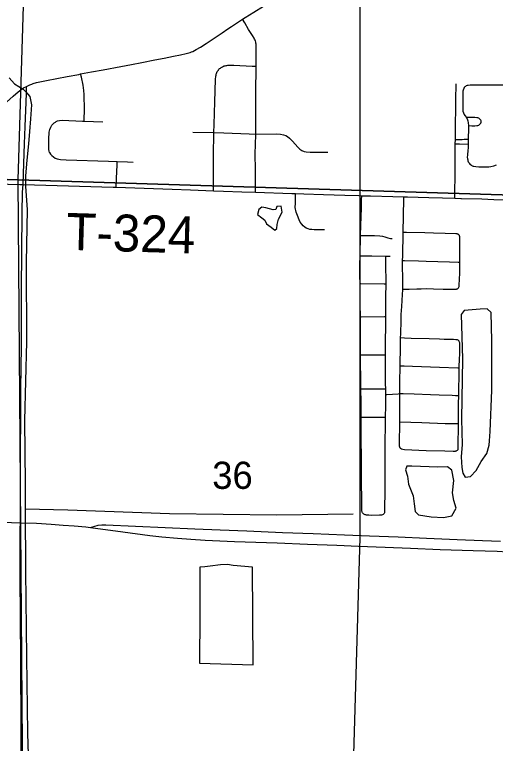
# Model space of a CAD drawing. Extents: x -59 to 43, y 0 to 22.
# Drawn here: x 24.142 to 24.882, y 15.472 to 16.594 of the extents above; entities that cross this region are included whole.
import ezdxf

# ---------------------------------------------------------------- set-up
doc = ezdxf.new("R2010")
doc.units = 0
for name, color, linetype in [('Default', 7, 'Continuous'), ('GM_X_City_Street', 7, 'Continuous'), ('GM_X_County_Road', 7, 'Continuous'), ('GM_X_Minor_Lake', 7, 'Continuous'), ('GM_X_Minor_River', 7, 'Continuous'), ('GM_X_Rail_Line', 7, 'Continuous'), ('GM_X_Section', 7, 'Continuous'), ('GM_X_Section_Text', 7, 'Continuous'), ('GM_X_Township_Road', 7, 'Continuous'), ('GM_X_Township_Road_Text', 7, 'Continuous'), ('GM_X_US_Route', 7, 'Continuous')]:
    doc.layers.add(name, color=color, linetype=linetype)

msp = doc.modelspace()

# ---------------------------------------------------------------- linework, layer by layer
at = {"layer": 'Default'}
for points in [[(23.5167, 17.352), (23.5167, 16.3587), (24.1477, 16.3396), (24.1786, 17.3434), (23.6345, 17.3468)], [(23.5167, 16.3587), (23.5167, 15.3547), (24.1557, 15.3353), (24.1477, 16.3396)]]:
    msp.add_lwpolyline(points, close=True, dxfattribs=at)
at = {"layer": 'GM_X_City_Street'}
msp.add_line((24.7127, 16.2225), (24.7201, 16.2224), dxfattribs=at)
for points in [[(24.5131, 16.4103), (24.5133, 16.4375), (24.5136, 16.4733), (24.5137, 16.5147), (24.514, 16.5361), (24.5141, 16.5448), (24.5141, 16.5466), (24.5139, 16.5485), (24.5136, 16.5503), (24.5133, 16.5519), (24.5128, 16.5535), (24.5122, 16.555), (24.5115, 16.5565), (24.5108, 16.5578), (24.5081, 16.562), (24.5023, 16.5714), (24.4965, 16.5813), (24.4931, 16.5869)], [(24.4481, 16.323), (24.4481, 16.3284), (24.4483, 16.3511), (24.4484, 16.3824), (24.4486, 16.407), (24.4488, 16.4125), (24.4491, 16.4249), (24.4503, 16.4597), (24.4514, 16.4944), (24.4518, 16.4993), (24.4521, 16.5009), (24.4524, 16.5022), (24.4529, 16.5037), (24.4534, 16.505), (24.4541, 16.5063), (24.4549, 16.5075), (24.4557, 16.5087), (24.4567, 16.5099), (24.4577, 16.5109), (24.4589, 16.5119), (24.4599, 16.5126), (24.4609, 16.5132), (24.4621, 16.5139), (24.4634, 16.5145), (24.4649, 16.5151), (24.4663, 16.5155), (24.4675, 16.5157), (24.4686, 16.5159), (24.4703, 16.5161), (24.4722, 16.5161), (24.4796, 16.5161), (24.5076, 16.5149), (24.5137, 16.5147)], [(24.2494, 16.4302), (24.2494, 16.4329), (24.2496, 16.4473), (24.2493, 16.471), (24.2489, 16.4772), (24.2477, 16.4853), (24.245, 16.4976), (24.2439, 16.5027)], [(24.1553, 16.3326), (24.1558, 16.3494), (24.1574, 16.395), (24.1584, 16.4221), (24.16, 16.4595), (24.1605, 16.4731), (24.1605, 16.4836)], [(24.8192, 16.3115), (24.8193, 16.3149), (24.8198, 16.3525), (24.82, 16.3882), (24.8201, 16.3952), (24.8203, 16.4021), (24.8205, 16.4115), (24.821, 16.4628), (24.8213, 16.4877)], [(24.8936, 16.4854), (24.8739, 16.4857), (24.849, 16.4856), (24.8428, 16.4855), (24.8399, 16.4852), (24.8384, 16.4848), (24.8371, 16.4843), (24.8359, 16.4835), (24.8348, 16.4827), (24.8339, 16.4817), (24.8332, 16.4805), (24.8322, 16.4778), (24.832, 16.4765), (24.8316, 16.4734), (24.8316, 16.4578), (24.8316, 16.4485), (24.8318, 16.4455), (24.8326, 16.4427), (24.834, 16.4402), (24.8347, 16.4389), (24.8374, 16.4355), (24.839, 16.4323), (24.8396, 16.4308), (24.8402, 16.4276), (24.8404, 16.4233), (24.8405, 16.4213), (24.8404, 16.415), (24.8398, 16.4067), (24.8397, 16.4023), (24.84, 16.3947)], [(24.8404, 16.4233), (24.8457, 16.4231), (24.8502, 16.423), (24.8533, 16.4232), (24.8548, 16.4236), (24.8562, 16.424), (24.8575, 16.4248), (24.8586, 16.4258), (24.8594, 16.4271), (24.8598, 16.4286), (24.8599, 16.4292), (24.8598, 16.4301), (24.8597, 16.4308), (24.8594, 16.4315), (24.8586, 16.4328), (24.8575, 16.4338), (24.8562, 16.4346), (24.8547, 16.435), (24.8532, 16.4353), (24.8502, 16.4356), (24.8472, 16.4356), (24.8374, 16.4355)], [(24.196, 16.3817), (24.1953, 16.3841), (24.1949, 16.3867), (24.1949, 16.3907), (24.1951, 16.4026), (24.1957, 16.4133), (24.1965, 16.4175), (24.1978, 16.421), (24.1994, 16.4237), (24.2015, 16.4261), (24.2033, 16.4276), (24.205, 16.4288)], [(24.205, 16.4288), (24.2064, 16.4296), (24.2084, 16.4304), (24.2114, 16.4311), (24.2157, 16.4315), (24.2467, 16.4303), (24.2494, 16.4302), (24.2782, 16.4291)], [(24.4166, 16.4132), (24.4488, 16.4125), (24.464, 16.4119), (24.5032, 16.4104), (24.5131, 16.4103)], [(24.5128, 16.3208), (24.5127, 16.3249), (24.5127, 16.3319), (24.5128, 16.3468), (24.5128, 16.3548), (24.5125, 16.3802), (24.5127, 16.3939), (24.5131, 16.4103)], [(24.5131, 16.4103), (24.5452, 16.4106), (24.5515, 16.4102), (24.5559, 16.4093), (24.5595, 16.408), (24.5623, 16.4065), (24.5653, 16.404), (24.5696, 16.3994), (24.5777, 16.39), (24.5808, 16.3872), (24.5843, 16.385), (24.5875, 16.3836), (24.591, 16.3828), (24.5968, 16.3825), (24.6242, 16.3822)], [(24.8203, 16.4021), (24.8254, 16.4021), (24.8305, 16.4021), (24.8339, 16.4022), (24.8397, 16.4023)], [(24.8201, 16.3952), (24.8268, 16.395), (24.84, 16.3947)], [(24.84, 16.3947), (24.8398, 16.3885), (24.8394, 16.3856), (24.8387, 16.3779), (24.8386, 16.3749), (24.8388, 16.3719), (24.8392, 16.3705), (24.8396, 16.3691), (24.8402, 16.3677), (24.8409, 16.3665), (24.8417, 16.3653), (24.8427, 16.3641), (24.8437, 16.3632), (24.8449, 16.3623), (24.8461, 16.3616), (24.8475, 16.361), (24.8488, 16.3606), (24.8518, 16.3601), (24.8564, 16.3599), (24.8688, 16.3597), (24.8718, 16.3599), (24.8748, 16.3604), (24.8792, 16.3615), (24.8835, 16.3631)], [(24.196, 16.3817), (24.1975, 16.3795), (24.1994, 16.3773), (24.202, 16.3751), (24.2046, 16.3734), (24.208, 16.372), (24.2129, 16.3711), (24.2215, 16.3704), (24.2868, 16.3685), (24.3002, 16.368), (24.3159, 16.3674), (24.3246, 16.3671)], [(24.2987, 16.3284), (24.299, 16.3423), (24.2999, 16.3624), (24.3002, 16.368)], [(24.619, 16.2629), (24.6032, 16.2629), (24.5997, 16.2632), (24.5966, 16.2636), (24.5936, 16.2644), (24.5907, 16.2656), (24.5887, 16.2669), (24.5863, 16.269), (24.5839, 16.2718), (24.5818, 16.2749), (24.58, 16.2782), (24.5772, 16.2851), (24.5753, 16.2903), (24.5747, 16.2924), (24.5743, 16.2945), (24.574, 16.297), (24.5742, 16.3039), (24.5746, 16.3173), (24.5746, 16.3187)], [(24.6744, 16.2542), (24.6748, 16.2693), (24.6757, 16.2966), (24.676, 16.3097), (24.6762, 16.3154)], [(24.74, 16.2588), (24.7411, 16.3105), (24.7412, 16.3137)], [(24.6736, 16.2226), (24.6736, 16.2234), (24.6744, 16.2542)], [(24.6744, 16.2542), (24.6755, 16.2542), (24.696, 16.2539), (24.7041, 16.2535), (24.7084, 16.2529), (24.712, 16.252), (24.7166, 16.2503), (24.7184, 16.2499), (24.7206, 16.2496), (24.7228, 16.2496)], [(24.7392, 16.2156), (24.7393, 16.2222), (24.74, 16.2588)], [(24.8273, 16.2131), (24.8273, 16.2148), (24.8273, 16.2184), (24.8271, 16.2454), (24.8271, 16.2494), (24.8271, 16.2513), (24.827, 16.252), (24.8269, 16.2527), (24.8267, 16.2533), (24.8264, 16.2539), (24.826, 16.2545), (24.8255, 16.255), (24.825, 16.2556), (24.8244, 16.256), (24.8237, 16.2563), (24.823, 16.2565), (24.8217, 16.2568), (24.8208, 16.2569), (24.8048, 16.2573), (24.7868, 16.2576), (24.7731, 16.258), (24.7452, 16.2587), (24.74, 16.2588)], [(24.6736, 16.1802), (24.6735, 16.1923), (24.6734, 16.2097), (24.6736, 16.2226)], [(24.6736, 16.2226), (24.6918, 16.2226), (24.7127, 16.2225)], [(24.7127, 16.2225), (24.7128, 16.2117), (24.7131, 16.1798)], [(24.7393, 16.1716), (24.7394, 16.1755), (24.7395, 16.186), (24.7393, 16.1934), (24.7391, 16.2018), (24.7392, 16.2156)], [(24.7392, 16.2156), (24.7418, 16.2156), (24.7638, 16.2151), (24.7756, 16.2148), (24.8111, 16.2137), (24.8247, 16.2132), (24.8273, 16.2131)], [(24.7393, 16.1716), (24.7423, 16.1717), (24.749, 16.1717), (24.761, 16.1719), (24.7675, 16.1722), (24.7751, 16.1724), (24.7864, 16.1723), (24.8013, 16.1718), (24.8174, 16.1713), (24.8195, 16.1713), (24.8203, 16.1713), (24.8211, 16.1714), (24.822, 16.1716), (24.8227, 16.1719), (24.8234, 16.1722), (24.824, 16.1725), (24.8247, 16.173), (24.8251, 16.1736), (24.8257, 16.1747), (24.826, 16.1755), (24.8261, 16.1762), (24.8263, 16.1778), (24.827, 16.1962), (24.8273, 16.2131)], [(24.6736, 16.1802), (24.6747, 16.1802), (24.7109, 16.1798), (24.7131, 16.1798)], [(24.6741, 16.1289), (24.6739, 16.1482), (24.6738, 16.1674), (24.6736, 16.1802)], [(24.7131, 16.1798), (24.713, 16.1596), (24.7129, 16.1375), (24.7129, 16.1327), (24.7129, 16.1293)], [(24.7361, 16.0971), (24.7362, 16.1021), (24.7367, 16.1239), (24.737, 16.1326), (24.7379, 16.1451), (24.7389, 16.1636), (24.7393, 16.1703), (24.7393, 16.1716)], [(24.6741, 16.1289), (24.6752, 16.1289), (24.7113, 16.1293), (24.7129, 16.1293)], [(24.6745, 16.0705), (24.6744, 16.0885), (24.6742, 16.0953), (24.6742, 16.1158), (24.6741, 16.1289)], [(24.7129, 16.1293), (24.7127, 16.1104), (24.7124, 16.0955), (24.7123, 16.0704)], [(24.7354, 16.0537), (24.7355, 16.0566), (24.7358, 16.0809), (24.7361, 16.0971)], [(24.7361, 16.0971), (24.7422, 16.0969), (24.7521, 16.0964), (24.78, 16.0954), (24.7956, 16.0949), (24.8029, 16.0947), (24.8108, 16.0945), (24.8176, 16.0944), (24.8208, 16.0943), (24.8216, 16.0943), (24.8224, 16.0941), (24.8231, 16.0939), (24.8241, 16.0935), (24.8249, 16.0928), (24.8254, 16.0922), (24.8258, 16.0916), (24.8263, 16.0904), (24.8264, 16.0897), (24.8265, 16.0888), (24.8266, 16.0878), (24.8266, 16.0862), (24.8266, 16.0826), (24.8265, 16.0768), (24.8259, 16.0594), (24.8258, 16.0569), (24.8256, 16.0506)], [(24.6745, 16.0705), (24.6826, 16.0705), (24.7019, 16.0704), (24.7123, 16.0704)], [(24.675, 16.0184), (24.6749, 16.032), (24.6746, 16.0605), (24.6745, 16.0705)], [(24.7123, 16.0704), (24.7123, 16.0632), (24.7123, 16.0477), (24.7122, 16.0316), (24.7123, 16.026), (24.7127, 16.018)], [(24.7349, 16.0108), (24.7351, 16.028), (24.7354, 16.0537)], [(24.7354, 16.0537), (24.7416, 16.0535), (24.7541, 16.0532), (24.7821, 16.0522), (24.7958, 16.0517), (24.8238, 16.0507), (24.8256, 16.0506)], [(24.8256, 16.0506), (24.8255, 16.0477), (24.825, 16.0077)], [(24.675, 16.0184), (24.6807, 16.0183), (24.7078, 16.0181), (24.7127, 16.018)], [(24.6752, 15.9744), (24.6752, 15.9779), (24.6752, 15.9984), (24.675, 16.017), (24.675, 16.0184)], [(24.7127, 16.018), (24.713, 16.0118), (24.713, 16.0095)], [(24.713, 16.0095), (24.7127, 15.9919), (24.7124, 15.9747)], [(24.713, 16.0095), (24.7148, 16.0096), (24.7321, 16.0107), (24.7349, 16.0108)], [(24.7348, 15.9676), (24.7349, 15.9704), (24.7348, 15.9872), (24.7349, 16.0108)], [(24.7349, 16.0108), (24.7402, 16.011), (24.757, 16.0103), (24.7819, 16.0094), (24.7955, 16.0087), (24.8154, 16.0083), (24.8204, 16.008), (24.825, 16.0077)], [(24.825, 16.0077), (24.8248, 15.995), (24.8245, 15.9646)], [(24.6752, 15.9744), (24.677, 15.9744), (24.6844, 15.9745), (24.6943, 15.9744), (24.7024, 15.9744), (24.7067, 15.9746), (24.7124, 15.9747)], [(24.7124, 15.9747), (24.7124, 15.9697), (24.7123, 15.9641), (24.712, 15.9337), (24.7118, 15.9039), (24.7118, 15.8896), (24.7116, 15.8642), (24.7114, 15.83), (24.7113, 15.8291), (24.7113, 15.8284), (24.7111, 15.8274), (24.7106, 15.8262), (24.7102, 15.8257), (24.7093, 15.8249), (24.708, 15.8242), (24.7069, 15.8238), (24.7059, 15.8236), (24.7048, 15.8235), (24.7036, 15.8235), (24.6916, 15.8234), (24.6873, 15.8235), (24.6854, 15.8237), (24.6836, 15.8239), (24.6823, 15.8241), (24.6814, 15.8244), (24.6806, 15.8247), (24.6794, 15.8255), (24.6787, 15.8261), (24.6781, 15.8268), (24.6775, 15.8275), (24.6769, 15.8283), (24.6767, 15.8289), (24.6764, 15.8301), (24.6763, 15.8312), (24.6763, 15.8327), (24.6763, 15.835), (24.6762, 15.8548), (24.6761, 15.8667), (24.6759, 15.8884), (24.6757, 15.9182), (24.6755, 15.9344), (24.6756, 15.9512), (24.6752, 15.9744)], [(24.8245, 15.9646), (24.8243, 15.9281), (24.8243, 15.9262), (24.8242, 15.9253), (24.8238, 15.9243), (24.8228, 15.9232), (24.8222, 15.9228), (24.8215, 15.9224), (24.8206, 15.9221), (24.8199, 15.9219), (24.8192, 15.9219), (24.8186, 15.9218), (24.8169, 15.9218), (24.8039, 15.9221), (24.7754, 15.9229), (24.7419, 15.9243), (24.7395, 15.9246), (24.7374, 15.9253), (24.7361, 15.9261), (24.7355, 15.9269), (24.7347, 15.9284), (24.7343, 15.93), (24.7341, 15.9324), (24.7348, 15.9676)], [(24.7348, 15.9676), (24.7689, 15.9662), (24.8044, 15.965), (24.8211, 15.9647), (24.8245, 15.9646)]]:
    msp.add_lwpolyline(points, dxfattribs=at)
at = {"layer": 'GM_X_County_Road'}
for points in [[(24.4931, 16.5869), (24.4972, 16.5896), (24.5102, 16.598), (24.5249, 16.6073), (24.5311, 16.6116), (24.5355, 16.6152), (24.5392, 16.6187), (24.5429, 16.6229), (24.5471, 16.6284), (24.5555, 16.6408), (24.5631, 16.6517), (24.5708, 16.6628), (24.5836, 16.6817), (24.5917, 16.6938)], [(24.2439, 16.5027), (24.2606, 16.5058), (24.2783, 16.5089), (24.3057, 16.5142), (24.3222, 16.5175), (24.338, 16.5205), (24.3581, 16.5243), (24.3722, 16.5269), (24.3868, 16.5299), (24.3977, 16.532), (24.4062, 16.534), (24.4122, 16.5359), (24.4143, 16.5367), (24.4163, 16.5375), (24.4218, 16.5403), (24.4284, 16.5441), (24.4368, 16.5496), (24.4491, 16.5579), (24.4616, 16.5661), (24.4703, 16.572), (24.476, 16.5757), (24.4915, 16.5858), (24.4931, 16.5869)], [(24.1605, 16.4836), (24.1659, 16.4862), (24.1687, 16.4873), (24.1711, 16.4882), (24.1758, 16.4895), (24.1916, 16.4929), (24.2233, 16.4989), (24.2411, 16.5021), (24.2439, 16.5027)], [(23.9912, 16.3373), (24.013, 16.3564), (24.0303, 16.3712), (24.0437, 16.3826), (24.0707, 16.406), (24.0928, 16.426), (24.1142, 16.4453), (24.13, 16.4595), (24.1402, 16.4686), (24.1476, 16.4751), (24.15, 16.477), (24.1526, 16.4789), (24.1561, 16.4812), (24.1605, 16.4836)]]:
    msp.add_lwpolyline(points, dxfattribs=at)
at = {"layer": 'GM_X_Minor_Lake'}
for p, q in [((24.5399, 16.2936), (24.5289, 16.2967)), ((24.831, 16.0645), (24.8299, 15.9714)), ((24.7933, 15.8978), (24.7534, 15.8994)), ((24.4272, 15.6702), (24.4266, 15.5961))]:
    msp.add_line(p, q, dxfattribs=at)
for points in [[(24.5289, 16.2967), (24.5228, 16.2975), (24.5179, 16.2941), (24.5159, 16.2865), (24.5228, 16.2812), (24.5273, 16.2777), (24.5296, 16.272), (24.5368, 16.2671), (24.5424, 16.2625), (24.5455, 16.2648), (24.5463, 16.2712), (24.5482, 16.2792), (24.5539, 16.2902), (24.5524, 16.2993), (24.5456, 16.2986), (24.544, 16.294), (24.5399, 16.2936)], [(24.8299, 15.9714), (24.8309, 15.9326), (24.829, 15.9137), (24.8301, 15.8973), (24.8316, 15.8882), (24.8353, 15.8821), (24.8433, 15.8832), (24.8524, 15.8927), (24.8601, 15.9063), (24.8688, 15.9189), (24.8723, 15.9314), (24.8727, 15.9382), (24.8739, 15.9526), (24.8763, 16.0161), (24.8766, 16.0921), (24.8752, 16.1354), (24.8691, 16.1415), (24.8585, 16.1408), (24.846, 16.14), (24.8338, 16.1385), (24.8293, 16.1325), (24.831, 16.0645)], [(24.7534, 15.8994), (24.7455, 15.8991), (24.7436, 15.8934), (24.7466, 15.8839), (24.7484, 15.8713), (24.7556, 15.8535), (24.7571, 15.8413), (24.7585, 15.8295), (24.7638, 15.8242), (24.7828, 15.8211), (24.8018, 15.8203), (24.8147, 15.8225), (24.8215, 15.8347), (24.8178, 15.8464), (24.8159, 15.8582), (24.8179, 15.8772), (24.8149, 15.8932), (24.8084, 15.8981), (24.7933, 15.8978)], [(24.4266, 15.5961), (24.5093, 15.5936), (24.5082, 15.7436), (24.4786, 15.7464), (24.4699, 15.7479), (24.4589, 15.7472), (24.443, 15.7453), (24.435, 15.7442), (24.4274, 15.7435), (24.4272, 15.6702)]]:
    msp.add_lwpolyline(points, dxfattribs=at)
at = {"layer": 'GM_X_Minor_River'}
for points in [[(24.1337, 16.4966), (24.1424, 16.4878), (24.1553, 16.4794), (24.1591, 16.476), (24.1655, 16.468), (24.1681, 16.4554), (24.1669, 16.4338), (24.1654, 16.4144), (24.1638, 16.3951), (24.1611, 16.37), (24.1591, 16.3461), (24.159, 16.3297), (24.1616, 16.294), (24.1602, 16.2127), (24.1606, 16.0904), (24.1576, 15.9696), (24.1584, 15.8727), (24.1587, 15.8336), (24.1591, 15.7378), (24.1606, 15.6052), (24.1622, 15.4882), (24.1653, 15.3891)], [(24.1587, 15.8336), (24.2243, 15.8319), (24.3806, 15.8264), (24.5457, 15.8244), (24.6633, 15.8256)]]:
    msp.add_lwpolyline(points, dxfattribs=at)
at = {"layer": 'GM_X_Rail_Line'}
msp.add_lwpolyline([(24.8595, 17.5703), (24.845, 16.9588), (24.842, 16.884), (24.8319, 16.8415), (24.8198, 16.8142), (24.7955, 16.7879), (24.6985, 16.7162), (24.6793, 16.6808), (24.6733, 16.6535), (24.6733, 15.7893), (24.6598, 15.3324), (24.6541, 14.7866), (24.6444, 14.1)], dxfattribs=at)
at = {"layer": 'GM_X_Section'}
for points in [[(24.1786, 17.3434), (24.4294, 17.3409), (25.1877, 17.3128), (25.1878, 17.2935), (25.173, 16.308), (24.1477, 16.3396)], [(24.1477, 16.3396), (25.173, 16.308), (25.1744, 16.294), (25.1667, 15.3001), (24.1557, 15.3353)]]:
    msp.add_lwpolyline(points, close=True, dxfattribs=at)
at = {"layer": 'GM_X_Township_Road'}
for p, q in [((24.5698, 16.3189), (24.5746, 16.3187)), ((24.8192, 16.3115), (24.8288, 16.3113)), ((24.1511, 15.8022), (24.1512, 15.8121))]:
    msp.add_line(p, q, dxfattribs=at)
for points in [[(23.9912, 16.3373), (24.0271, 16.3366), (24.0755, 16.3352), (24.114, 16.3339), (24.1506, 16.3328), (24.1553, 16.3326)], [(24.1512, 15.8121), (24.1513, 15.8224), (24.1512, 15.8783), (24.152, 16.0182), (24.1527, 16.0835), (24.153, 16.1706), (24.1537, 16.2887), (24.1546, 16.3207), (24.1553, 16.3326)], [(24.1553, 16.3326), (24.2078, 16.3311), (24.2941, 16.3285), (24.2987, 16.3284)], [(24.2987, 16.3284), (24.3848, 16.3253), (24.4131, 16.3242), (24.4481, 16.323)], [(24.4481, 16.323), (24.4636, 16.3224), (24.4916, 16.3215), (24.5128, 16.3208)], [(24.5128, 16.3208), (24.5689, 16.3189), (24.5698, 16.3189)], [(24.5746, 16.3187), (24.5872, 16.3183), (24.6176, 16.3174), (24.6503, 16.3162), (24.6716, 16.3155), (24.6762, 16.3154)], [(24.6762, 16.3154), (24.6895, 16.315), (24.7243, 16.3142), (24.7412, 16.3137), (24.7466, 16.3136), (24.7792, 16.3125), (24.8004, 16.312), (24.8192, 16.3115)], [(24.8288, 16.3113), (24.8297, 16.3113), (24.861, 16.3104)], [(24.861, 16.3104), (24.8795, 16.3097), (24.8973, 16.3092), (24.9145, 16.3087), (24.94, 16.3082), (24.9475, 16.3079), (24.9553, 16.3076), (25.0297, 16.3044)], [(24.154, 15.3313), (24.1533, 15.3498), (24.1528, 15.4026), (24.1519, 15.5954), (24.1515, 15.67), (24.1511, 15.726), (24.151, 15.7913), (24.1511, 15.8022)]]:
    msp.add_lwpolyline(points, dxfattribs=at)
at = {"layer": 'GM_X_US_Route'}
for points in [[(24.1091, 15.8137), (24.1512, 15.8121), (24.1761, 15.8112), (24.1986, 15.8098), (24.2171, 15.8085), (24.2339, 15.8072), (24.2519, 15.8056), (24.2592, 15.8048)], [(24.2592, 15.8048), (24.2642, 15.8065), (24.2706, 15.8081), (24.2767, 15.8087), (24.2825, 15.8087), (24.4194, 15.8027), (24.4585, 15.801), (24.4995, 15.7994), (24.5542, 15.7973), (24.6014, 15.7954), (24.6498, 15.7937), (24.6883, 15.792), (24.7324, 15.7903), (24.7759, 15.7884), (24.8231, 15.7865), (24.8622, 15.785), (24.8896, 15.7839)], [(24.2592, 15.8048), (24.3086, 15.7982), (24.3505, 15.7926), (24.369, 15.7905), (24.3931, 15.7881), (24.4135, 15.7866), (24.4352, 15.7854), (24.4806, 15.7834), (24.5464, 15.7811), (24.593, 15.7792), (24.6377, 15.7774), (24.6713, 15.776), (24.7123, 15.7747), (24.7514, 15.7731), (24.7967, 15.7711), (24.8477, 15.7694), (24.8843, 15.7681), (24.9007, 15.7675), (24.921, 15.7668), (24.9639, 15.7652), (25.0776, 15.7608), (25.1478, 15.7579), (25.1663, 15.7571), (25.1701, 15.757)]]:
    msp.add_lwpolyline(points, dxfattribs=at)

# ---------------------------------------------------------------- texts
at = {"layer": 'GM_X_Section_Text'}
msp.add_text('36', height=0.04186, rotation=0, dxfattribs=at).set_placement((24.4463, 15.8642))
at = {"layer": 'GM_X_Township_Road_Text'}
msp.add_text('T-324', height=0.05682, rotation=358.315, dxfattribs=at).set_placement((24.221, 16.2322))

doc.saveas('drawing.dxf')
